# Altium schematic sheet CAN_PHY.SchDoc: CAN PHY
size A4; Author: Daniela Catanzaro; CompanyName: Arduino srl; DocumentNumber: ASX00055; SheetNumber: 5; SheetTotal: 10; RevAuthor: Daniela Catanzaro
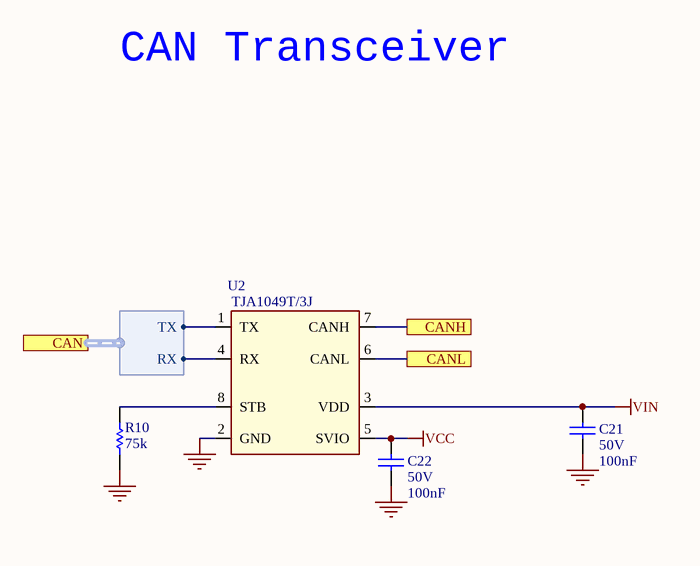
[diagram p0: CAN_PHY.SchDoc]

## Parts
C21  value 100nF  Voltage: 50V  [CAP-0603]  (hidden comment: 0603B104K500CT)
C22  value 100nF  Voltage: 50V  [CAP-0603]  (hidden comment: 0603B104K500CT)
R10  value 75k  [RES-0603]  (hidden comment: CRCW060375K0FKEAC)
U2  TJA1049T/3J  [TJA1049T_3J-Footprint-1]

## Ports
CAN (harness CAN), CANH, CANL

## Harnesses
CAN: RX, TX

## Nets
GND: C21.2 C22.2 R10.1 U2.2(GND)
VCC: C22.1 U2.5(SVIO)
VIN: C21.1 U2.3(VDD)
CANH: U2.7(CANH) ; port CANH
CANL: U2.6(CANL) ; port CANL
NetR10_2: R10.2 U2.8(STB)
NetU2_1: U2.1(TX) ; port CAN.TX
NetU2_4: U2.4(RX) ; port CAN.RX

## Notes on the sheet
- CAN Transceiver

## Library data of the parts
C21 C22 = C0043-A.14: CAP CHIP 0603 100nF 10% 50V X7R; Manufacturer: Walsin; Code Arduino: 0015
R10 = R0098-A.22: RES CHIP 0603 75k 1% 1/10W; Manufacturer: Vishay; Power: 100mW; Code Arduino: 0376; Temperature coefficient: 100ppm
U2 = U0114-A.7: IC CAN TRANSCEIVER 1Mbps STBY 5.25V SOIC8; Manufacturer: NXP; Code Arduino: U0114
